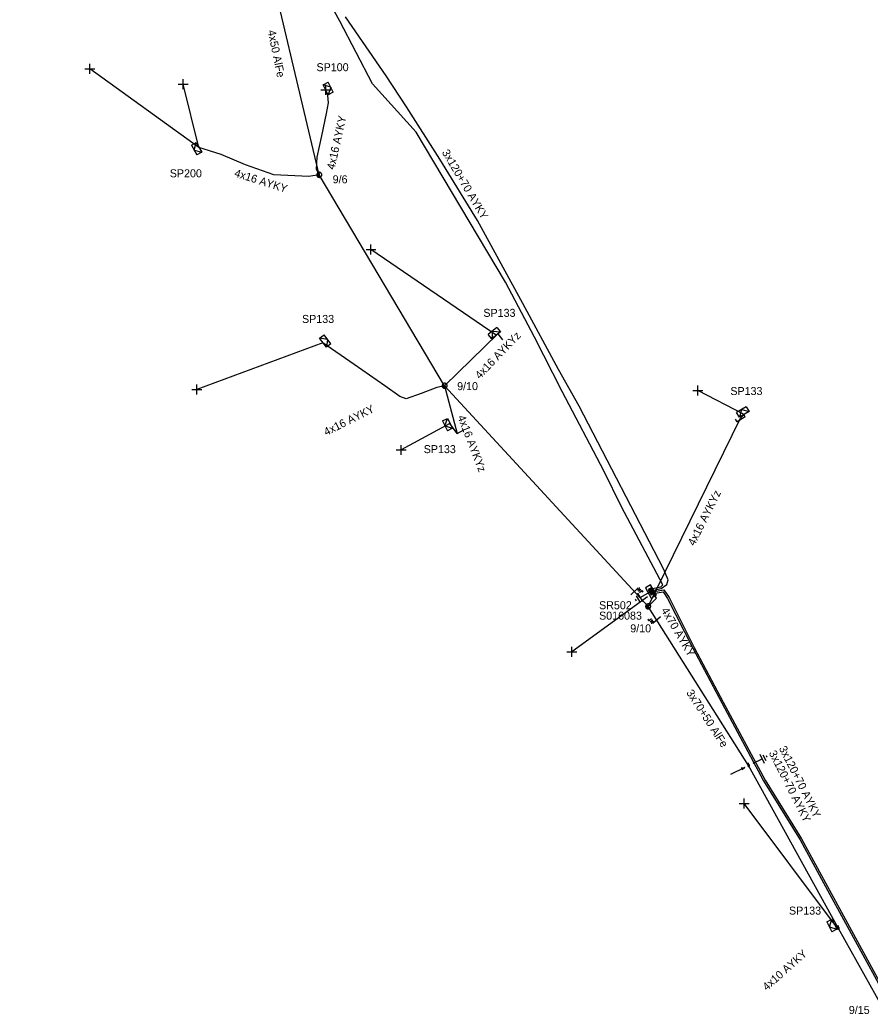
# Model space of a CAD drawing. Extents: x -717562 to -713845, y -1151196 to -1143903.
# Drawn here: x -717142.1 to -717035.8, y -1144570.4 to -1144446.2 of the extents above; entities that cross this region are included whole.
import ezdxf

# ---------------------------------------------------------------- set-up
doc = ezdxf.new("R2010")
doc.units = 0
for name, color, linetype in [('Vrstva 1', 7, 'Continuous'), ('Vrstva 12', 7, 'Continuous'), ('Vrstva 13', 7, 'Continuous'), ('Vrstva 14', 7, 'Continuous'), ('Vrstva 15', 7, 'Continuous'), ('Vrstva 18', 7, 'Continuous'), ('Vrstva 2', 7, 'Continuous'), ('Vrstva 28', 7, 'Continuous'), ('Vrstva 29', 7, 'Continuous'), ('Vrstva 30', 7, 'Continuous'), ('Vrstva 31', 7, 'Continuous'), ('Vrstva 33', 7, 'Continuous'), ('Vrstva 34', 7, 'Continuous'), ('Vrstva 5', 7, 'Continuous'), ('Vrstva 52', 7, 'Continuous'), ('Vrstva 54', 7, 'Continuous'), ('Vrstva 55', 7, 'Continuous'), ('Vrstva 59', 7, 'Continuous'), ('Vrstva 6', 7, 'Continuous'), ('Vrstva 8', 7, 'Continuous'), ('Vrstva 9', 7, 'Continuous')]:
    doc.layers.add(name, color=color, linetype=linetype)

# ---------------------------------------------------------------- blocks, each defined once
blk = doc.blocks.new('NN440')
at = {"layer": 'Vrstva 2'}
for points in [[(0.63, 0), (0.63, 0.06), (0.62, 0.13), (0.6, 0.19), (0.58, 0.25), (0.55, 0.31), (0.51, 0.37), (0.47, 0.42), (0.42, 0.46), (0.37, 0.51), (0.32, 0.54), (0.26, 0.57), (0.2, 0.59), (0.13, 0.61), (0.07, 0.62), (0, 0.63), (-0.06, 0.62), (-0.13, 0.61), (-0.19, 0.59), (-0.26, 0.57), (-0.31, 0.54), (-0.37, 0.51), (-0.42, 0.46), (-0.47, 0.42), (-0.51, 0.37), (-0.54, 0.31), (-0.57, 0.25), (-0.6, 0.19), (-0.62, 0.13), (-0.63, 0.06), (-0.63, 0), (-0.63, -0.07), (-0.62, -0.14), (-0.6, -0.2), (-0.57, -0.26), (-0.54, -0.32), (-0.51, -0.37), (-0.47, -0.43), (-0.42, -0.47), (-0.37, -0.51), (-0.31, -0.55), (-0.26, -0.58), (-0.19, -0.6), (-0.13, -0.62), (-0.06, -0.63), (0, -0.63), (0.07, -0.63), (0.13, -0.62), (0.2, -0.6), (0.26, -0.58), (0.32, -0.55), (0.37, -0.51), (0.42, -0.47), (0.47, -0.43), (0.51, -0.37), (0.55, -0.32), (0.58, -0.26), (0.6, -0.2), (0.62, -0.14), (0.63, -0.07), (0.63, 0)], [(-0.63, 0), (0.63, 0)], [(-0.6, -0.18), (0.57, -0.18)], [(-0.51, -0.32), (0.5, -0.32)], [(-0.37, -0.47), (0.35, -0.47)]]:
    blk.add_lwpolyline(points, dxfattribs=at)
blk = doc.blocks.new('NN840')
at = {"layer": 'Vrstva 15'}
for points in [[(0, 0.62), (0, -0.63)], [(-0.75, -0.71), (-0.75, -0.66)], [(-0.73, -0.76), (-0.75, -0.71)], [(-0.66, -0.8), (-0.73, -0.76)], [(-0.63, -0.8), (-0.66, -0.8)], [(-0.56, -0.76), (-0.63, -0.8)], [(-0.54, -0.71), (-0.56, -0.76)], [(-0.54, -0.38), (-0.54, -0.71)], [(-0.33, -0.38), (-0.33, -0.8)], [(-0.33, -0.64), (-0.13, -0.38)], [(-0.26, -0.56), (-0.09, -0.8)]]:
    blk.add_lwpolyline(points, dxfattribs=at)
blk = doc.blocks.new('NN565')
at = {"layer": 'Vrstva 2'}
for points in [[(0.01, 0.53), (0.01, 2.53)], [(0.16, 0.94), (0.01, 0.53), (-0.12, 0.94)]]:
    blk.add_lwpolyline(points, dxfattribs=at)
blk = doc.blocks.new('NN800')
at = {"layer": 'Vrstva 1'}
for points in [[(-0.44, 0.44), (0.44, -0.44)], [(-0.44, -0.44), (0.44, 0.44)]]:
    blk.add_lwpolyline(points, dxfattribs=at)
blk = doc.blocks.new('NN620')
at = {"layer": 'Vrstva 8'}
for points in [[(0.75, 0), (-0.75, 0)], [(-0.75, 0), (-0.75, -0.75)], [(0.75, -0.75), (0.75, 0)], [(-0.75, -0.75), (0.75, -0.75)], [(0.37, -0.18), (-0.38, -0.18)], [(-0.38, -0.18), (-0.38, -0.56)], [(-0.38, -0.56), (0.37, -0.56)], [(0.32, -0.23), (-0.33, -0.23)], [(-0.33, -0.23), (-0.33, -0.51)], [(-0.33, -0.51), (0.32, -0.51)], [(0.27, -0.27), (-0.28, -0.27)], [(-0.28, -0.27), (-0.28, -0.46)], [(-0.28, -0.46), (0.27, -0.46)], [(0.23, -0.32), (-0.23, -0.32)], [(-0.23, -0.32), (-0.23, -0.42)], [(-0.23, -0.42), (0.23, -0.42)], [(-0.19, -0.37), (0.19, -0.37)], [(0.23, -0.42), (0.23, -0.32)], [(0.27, -0.46), (0.27, -0.27)], [(0.32, -0.51), (0.32, -0.23)], [(0.37, -0.56), (0.37, -0.18)]]:
    blk.add_lwpolyline(points, dxfattribs=at)
blk = doc.blocks.new('NN630')
at = {"layer": 'Vrstva 9'}
for points in [[(0, -0.7), (-0.7, 0)], [(-0.7, -0.7), (-0.7, 0), (0.7, 0), (0.7, -0.7)], [(-0.7, -0.7), (0.7, -0.7)], [(0, -0.7), (0.7, 0)]]:
    blk.add_lwpolyline(points, dxfattribs=at)
blk = doc.blocks.new('NN810')
at = {"layer": 'Vrstva 14'}
for points in [[(0, -0.64), (0, -1.89)], [(0.63, -1.89), (-0.62, -1.89)], [(0.39, -2.2), (-0.4, -2.2)], [(0, -2.52), (-0.12, -2.52)], [(0.14, -2.52), (0, -2.52)]]:
    blk.add_lwpolyline(points, dxfattribs=at)
blk = doc.blocks.new('NN500')
at = {"layer": 'Vrstva 2'}
for points in [[(0, -0.24), (0.02, -0.23), (0.05, -0.23), (0.07, -0.22), (0.09, -0.22), (0.12, -0.2), (0.14, -0.19), (0.16, -0.18), (0.17, -0.16), (0.19, -0.14), (0.2, -0.12), (0.21, -0.1), (0.22, -0.07), (0.23, -0.05), (0.23, -0.02), (0.23, 0), (0.23, 0.02), (0.23, 0.05), (0.22, 0.07), (0.21, 0.1), (0.2, 0.12), (0.19, 0.14), (0.17, 0.16), (0.16, 0.17), (0.14, 0.19), (0.12, 0.2), (0.09, 0.21), (0.07, 0.22), (0.05, 0.23), (0.02, 0.23), (0, 0.23), (-0.03, 0.23), (-0.05, 0.23), (-0.07, 0.22), (-0.1, 0.21), (-0.12, 0.2), (-0.14, 0.19), (-0.16, 0.17), (-0.18, 0.16), (-0.19, 0.14), (-0.2, 0.12), (-0.22, 0.1), (-0.22, 0.07), (-0.23, 0.05), (-0.23, 0.02), (-0.24, 0), (-0.23, -0.02), (-0.23, -0.05), (-0.22, -0.07), (-0.22, -0.1), (-0.2, -0.12), (-0.19, -0.14), (-0.18, -0.16), (-0.16, -0.18), (-0.14, -0.19), (-0.12, -0.2), (-0.1, -0.22), (-0.07, -0.22), (-0.05, -0.23), (-0.03, -0.23), (0, -0.24)], [(0, -0.24), (0.02, -0.23), (0.05, -0.23), (0.07, -0.22), (0.09, -0.22), (0.12, -0.2), (0.14, -0.19), (0.16, -0.18), (0.17, -0.16), (0.19, -0.14), (0.2, -0.12), (0.21, -0.1), (0.22, -0.07), (0.23, -0.05), (0.23, -0.02), (0.23, 0), (0.23, 0.02), (0.23, 0.05), (0.22, 0.07), (0.21, 0.1), (0.2, 0.12), (0.19, 0.14), (0.17, 0.16), (0.16, 0.17), (0.14, 0.19), (0.12, 0.2), (0.09, 0.21), (0.07, 0.22), (0.05, 0.23), (0.02, 0.23), (0, 0.23), (-0.03, 0.23), (-0.05, 0.23), (-0.07, 0.22), (-0.1, 0.21), (-0.12, 0.2), (-0.14, 0.19), (-0.16, 0.17), (-0.18, 0.16), (-0.19, 0.14), (-0.2, 0.12), (-0.22, 0.1), (-0.22, 0.07), (-0.23, 0.05), (-0.23, 0.02), (-0.24, 0), (-0.23, -0.02), (-0.23, -0.05), (-0.22, -0.07), (-0.22, -0.1), (-0.2, -0.12), (-0.19, -0.14), (-0.18, -0.16), (-0.16, -0.18), (-0.14, -0.19), (-0.12, -0.2), (-0.1, -0.22), (-0.07, -0.22), (-0.05, -0.23), (-0.03, -0.23), (0, -0.24)], [(0, -0.21), (0.02, -0.2), (0.04, -0.2), (0.06, -0.2), (0.08, -0.19), (0.1, -0.18), (0.12, -0.17), (0.14, -0.15), (0.15, -0.14), (0.16, -0.12), (0.18, -0.1), (0.19, -0.08), (0.19, -0.06), (0.2, -0.04), (0.2, -0.02), (0.2, 0), (0.2, 0.02), (0.2, 0.04), (0.19, 0.06), (0.19, 0.08), (0.18, 0.1), (0.16, 0.12), (0.15, 0.14), (0.14, 0.15), (0.12, 0.17), (0.1, 0.18), (0.08, 0.19), (0.06, 0.19), (0.04, 0.2), (0.02, 0.2), (0, 0.2), (-0.02, 0.2), (-0.04, 0.2), (-0.06, 0.19), (-0.08, 0.19), (-0.1, 0.18), (-0.12, 0.17), (-0.14, 0.15), (-0.15, 0.14), (-0.17, 0.12), (-0.18, 0.1), (-0.19, 0.08), (-0.2, 0.06), (-0.2, 0.04), (-0.21, 0.02), (-0.21, 0), (-0.21, -0.02), (-0.2, -0.04), (-0.2, -0.06), (-0.19, -0.08), (-0.18, -0.1), (-0.17, -0.12), (-0.15, -0.14), (-0.14, -0.15), (-0.12, -0.17), (-0.1, -0.18), (-0.08, -0.19), (-0.06, -0.2), (-0.04, -0.2), (-0.02, -0.2), (0, -0.21)], [(0, -0.18), (0.02, -0.18), (0.04, -0.17), (0.05, -0.17), (0.07, -0.16), (0.09, -0.15), (0.1, -0.14), (0.12, -0.13), (0.13, -0.12), (0.14, -0.1), (0.15, -0.09), (0.16, -0.07), (0.17, -0.05), (0.17, -0.04), (0.17, -0.02), (0.17, 0), (0.17, 0.02), (0.17, 0.04), (0.17, 0.05), (0.16, 0.07), (0.15, 0.09), (0.14, 0.1), (0.13, 0.12), (0.12, 0.13), (0.1, 0.14), (0.09, 0.15), (0.07, 0.16), (0.05, 0.17), (0.04, 0.17), (0.02, 0.17), (0, 0.18), (-0.02, 0.17), (-0.04, 0.17), (-0.06, 0.17), (-0.07, 0.16), (-0.09, 0.15), (-0.1, 0.14), (-0.12, 0.13), (-0.13, 0.12), (-0.14, 0.1), (-0.15, 0.09), (-0.16, 0.07), (-0.17, 0.05), (-0.17, 0.04), (-0.18, 0.02), (-0.18, 0), (-0.18, -0.02), (-0.17, -0.04), (-0.17, -0.05), (-0.16, -0.07), (-0.15, -0.09), (-0.14, -0.1), (-0.13, -0.12), (-0.12, -0.13), (-0.1, -0.14), (-0.09, -0.15), (-0.07, -0.16), (-0.06, -0.17), (-0.04, -0.17), (-0.02, -0.18), (0, -0.18)], [(0, -0.15), (0.01, -0.15), (0.03, -0.14), (0.04, -0.14), (0.06, -0.13), (0.07, -0.13), (0.08, -0.12), (0.1, -0.11), (0.11, -0.1), (0.12, -0.09), (0.13, -0.07), (0.13, -0.06), (0.14, -0.05), (0.14, -0.03), (0.14, -0.02), (0.14, 0), (0.14, 0.01), (0.14, 0.03), (0.14, 0.04), (0.13, 0.06), (0.13, 0.07), (0.12, 0.09), (0.11, 0.1), (0.1, 0.11), (0.08, 0.12), (0.07, 0.13), (0.06, 0.13), (0.04, 0.14), (0.03, 0.14), (0.01, 0.14), (0, 0.15), (-0.02, 0.14), (-0.03, 0.14), (-0.05, 0.14), (-0.06, 0.13), (-0.07, 0.13), (-0.09, 0.12), (-0.1, 0.11), (-0.11, 0.1), (-0.12, 0.09), (-0.13, 0.07), (-0.13, 0.06), (-0.14, 0.04), (-0.14, 0.03), (-0.15, 0.01), (-0.15, 0), (-0.15, -0.02), (-0.14, -0.03), (-0.14, -0.05), (-0.13, -0.06), (-0.13, -0.07), (-0.12, -0.09), (-0.11, -0.1), (-0.1, -0.11), (-0.09, -0.12), (-0.07, -0.13), (-0.06, -0.13), (-0.05, -0.14), (-0.03, -0.14), (-0.02, -0.15), (0, -0.15)], [(0, -0.12), (0.01, -0.12), (0.02, -0.11), (0.03, -0.11), (0.05, -0.11), (0.06, -0.1), (0.07, -0.09), (0.08, -0.09), (0.09, -0.08), (0.09, -0.07), (0.1, -0.06), (0.11, -0.05), (0.11, -0.04), (0.11, -0.02), (0.11, -0.01), (0.12, 0), (0.11, 0.01), (0.11, 0.02), (0.11, 0.04), (0.11, 0.05), (0.1, 0.06), (0.09, 0.07), (0.09, 0.08), (0.08, 0.09), (0.07, 0.09), (0.06, 0.1), (0.05, 0.11), (0.03, 0.11), (0.02, 0.11), (0.01, 0.12), (0, 0.12), (-0.01, 0.12), (-0.03, 0.11), (-0.04, 0.11), (-0.05, 0.11), (-0.06, 0.1), (-0.07, 0.09), (-0.08, 0.09), (-0.09, 0.08), (-0.1, 0.07), (-0.1, 0.06), (-0.11, 0.05), (-0.11, 0.04), (-0.12, 0.02), (-0.12, 0.01), (-0.12, 0), (-0.12, -0.01), (-0.12, -0.02), (-0.11, -0.04), (-0.11, -0.05), (-0.1, -0.06), (-0.1, -0.07), (-0.09, -0.08), (-0.08, -0.09), (-0.07, -0.09), (-0.06, -0.1), (-0.05, -0.11), (-0.04, -0.11), (-0.03, -0.11), (-0.01, -0.12), (0, -0.12)], [(0, -0.09), (0.01, -0.09), (0.02, -0.09), (0.03, -0.08), (0.03, -0.08), (0.04, -0.08), (0.05, -0.07), (0.06, -0.07), (0.06, -0.06), (0.07, -0.05), (0.07, -0.04), (0.08, -0.04), (0.08, -0.03), (0.08, -0.02), (0.09, -0.01), (0.09, 0), (0.09, 0.01), (0.08, 0.02), (0.08, 0.03), (0.08, 0.03), (0.07, 0.04), (0.07, 0.05), (0.06, 0.06), (0.06, 0.06), (0.05, 0.07), (0.04, 0.07), (0.03, 0.08), (0.03, 0.08), (0.02, 0.08), (0.01, 0.09), (0, 0.09), (-0.01, 0.09), (-0.02, 0.08), (-0.03, 0.08), (-0.04, 0.08), (-0.04, 0.07), (-0.05, 0.07), (-0.06, 0.06), (-0.07, 0.06), (-0.07, 0.05), (-0.08, 0.04), (-0.08, 0.03), (-0.08, 0.03), (-0.09, 0.02), (-0.09, 0.01), (-0.09, 0), (-0.09, -0.01), (-0.09, -0.02), (-0.08, -0.03), (-0.08, -0.04), (-0.08, -0.04), (-0.07, -0.05), (-0.07, -0.06), (-0.06, -0.07), (-0.05, -0.07), (-0.04, -0.08), (-0.04, -0.08), (-0.03, -0.08), (-0.02, -0.09), (-0.01, -0.09), (0, -0.09)], [(0, -0.06), (0, -0.06), (0.01, -0.06), (0.02, -0.05), (0.02, -0.05), (0.03, -0.05), (0.03, -0.05), (0.04, -0.04), (0.04, -0.04), (0.05, -0.03), (0.05, -0.03), (0.05, -0.02), (0.05, -0.02), (0.05, -0.01), (0.06, -0.01), (0.06, 0), (0.06, 0.01), (0.05, 0.01), (0.05, 0.02), (0.05, 0.02), (0.05, 0.03), (0.05, 0.03), (0.04, 0.04), (0.04, 0.04), (0.03, 0.05), (0.03, 0.05), (0.02, 0.05), (0.02, 0.05), (0.01, 0.06), (0, 0.06), (0, 0.06), (-0.01, 0.06), (-0.01, 0.06), (-0.02, 0.05), (-0.02, 0.05), (-0.03, 0.05), (-0.03, 0.05), (-0.04, 0.04), (-0.04, 0.04), (-0.05, 0.03), (-0.05, 0.03), (-0.05, 0.02), (-0.06, 0.02), (-0.06, 0.01), (-0.06, 0.01), (-0.06, 0), (-0.06, -0.01), (-0.06, -0.01), (-0.06, -0.02), (-0.05, -0.02), (-0.05, -0.03), (-0.05, -0.03), (-0.04, -0.04), (-0.04, -0.04), (-0.03, -0.05), (-0.03, -0.05), (-0.02, -0.05), (-0.02, -0.05), (-0.01, -0.06), (-0.01, -0.06), (0, -0.06)], [(0, -0.03), (0, -0.03), (0, -0.03), (0.01, -0.03), (0.01, -0.03), (0.01, -0.02), (0.02, -0.02), (0.02, -0.02), (0.02, -0.02), (0.02, -0.02), (0.02, -0.01), (0.02, -0.01), (0.03, -0.01), (0.03, -0.01), (0.03, 0), (0.03, 0), (0.03, 0), (0.03, 0.01), (0.03, 0.01), (0.02, 0.01), (0.02, 0.01), (0.02, 0.02), (0.02, 0.02), (0.02, 0.02), (0.02, 0.02), (0.01, 0.02), (0.01, 0.02), (0.01, 0.03), (0, 0.03), (0, 0.03), (0, 0.03), (0, 0.03), (-0.01, 0.03), (-0.01, 0.03), (-0.01, 0.02), (-0.02, 0.02), (-0.02, 0.02), (-0.02, 0.02), (-0.02, 0.02), (-0.02, 0.02), (-0.03, 0.01), (-0.03, 0.01), (-0.03, 0.01), (-0.03, 0.01), (-0.03, 0), (-0.03, 0), (-0.03, 0), (-0.03, -0.01), (-0.03, -0.01), (-0.03, -0.01), (-0.03, -0.01), (-0.02, -0.02), (-0.02, -0.02), (-0.02, -0.02), (-0.02, -0.02), (-0.02, -0.02), (-0.01, -0.03), (-0.01, -0.03), (-0.01, -0.03), (0, -0.03), (0, -0.03)], [(0.23, 0), (0.7, 0)]]:
    blk.add_lwpolyline(points, dxfattribs=at)
blk = doc.blocks.new('NN510')
at = {"layer": 'Vrstva 2'}
blk.add_lwpolyline([(0, 0), (0, 0.94)], dxfattribs=at)
blk = doc.blocks.new('NN515')
at = {"layer": 'Vrstva 2'}
for points in [[(-0.59, 0.18), (0.59, 0.18)], [(-0.59, 0.18), (-0.59, -0.18)], [(0.59, 0.18), (0.59, -0.18)]]:
    blk.add_lwpolyline(points, dxfattribs=at)

msp = doc.modelspace()

# ---------------------------------------------------------------- linework, layer by layer
at = {"layer": 'Vrstva 1'}
for points in [[(-717063.54, -1144519.5), (-717088.98, -1144491.92), (-717104.65, -1144465.56), (-717112.11, -1144434.03), (-717129.32, -1144395.14), (-717142.08, -1144353.91)], [(-717034.22, -1144569.65), (-717039.77, -1144559.73), (-717050.99, -1144539.38), (-717063.54, -1144519.5)]]:
    msp.add_lwpolyline(points, dxfattribs=at)
at = {"layer": 'Vrstva 5'}
for points in [[(-717063.54, -1144519.5), (-717062.48, -1144518.46), (-717062.73, -1144518.05)], [(-717062.79, -1144517.65), (-717061.58, -1144517.41), (-717060.93, -1144518.39), (-717057.78, -1144524.64), (-717054.16, -1144531.46), (-717048.93, -1144541.21), (-717044.37, -1144548.56), (-717040.64, -1144555.42), (-717033.37, -1144568.72)], [(-717062.67, -1144517.85), (-717061.66, -1144517.66), (-717061.11, -1144518.49), (-717057.96, -1144524.73), (-717054.34, -1144531.56), (-717049.11, -1144541.31), (-717044.55, -1144548.66), (-717040.82, -1144555.52), (-717033.55, -1144568.82)]]:
    msp.add_lwpolyline(points, dxfattribs=at)
at = {"layer": 'Vrstva 52'}
for points in [[(-717063.01, -1144517.27), (-717061.95, -1144517.07), (-717061.69, -1144516.79), (-717066.89, -1144507.06), (-717069.09, -1144502.54), (-717074.3, -1144492.66), (-717077.75, -1144485.87), (-717081.38, -1144478.98), (-717092.54, -1144460.21), (-717097.98, -1144454.18), (-717102.09, -1144446.37), (-717104.09, -1144442.69)], [(-717062.87, -1144517.45), (-717061.93, -1144517.27), (-717061.22, -1144516.76), (-717061.05, -1144516.17), (-717061.63, -1144514.81), (-717072.15, -1144494.49), (-717074.74, -1144489.87), (-717079.22, -1144481.64), (-717084.86, -1144471.25), (-717089.59, -1144463.62), (-717093.74, -1144457.05), (-717096.28, -1144453.2), (-717101.37, -1144445.81)], [(-717104.65, -1144465.56), (-717105.02, -1144464.85), (-717104.93, -1144463.35), (-717104.34, -1144460.69), (-717103.73, -1144457.91), (-717103.51, -1144456.55), (-717103.57, -1144455.63), (-717103.84, -1144454.93)], [(-717104.65, -1144465.56), (-717105.94, -1144465.77), (-717110.34, -1144465.58), (-717113.87, -1144464.32), (-717116.92, -1144463.03), (-717119.69, -1144462.13)], [(-717088.98, -1144491.92), (-717089.97, -1144492.15), (-717091.9, -1144492.9), (-717093.8, -1144493.57), (-717094.58, -1144493.27), (-717096.47, -1144491.95), (-717100.28, -1144489.27), (-717104.19, -1144486.55)], [(-717039.77, -1144559.73), (-717040.26, -1144559.22)]]:
    msp.add_lwpolyline(points, dxfattribs=at)
at = {"layer": 'Vrstva 54'}
for points in [[(-717088.98, -1144491.92), (-717082.35, -1144485.44), (-717082.56, -1144485.62)], [(-717088.98, -1144491.92), (-717087.42, -1144497.88), (-717088.32, -1144496.62)], [(-717063.54, -1144519.5), (-717052.01, -1144495.96), (-717051.54, -1144495.51)]]:
    msp.add_lwpolyline(points, dxfattribs=at)
at = {"layer": 'Vrstva 59'}
for points in [[(-717119.69, -1144462.13), (-717133.32, -1144452.32)], [(-717119.69, -1144462.13), (-717121.68, -1144454.22)], [(-717082.56, -1144485.62), (-717098.19, -1144474.88)], [(-717104.19, -1144486.55), (-717119.94, -1144492.38)], [(-717051.54, -1144495.51), (-717057.32, -1144492.52)], [(-717088.32, -1144496.62), (-717094.4, -1144499.95)], [(-717063.61, -1144518.31), (-717073.09, -1144525.17)], [(-717040.26, -1144559.22), (-717051.56, -1144544.13)]]:
    msp.add_lwpolyline(points, dxfattribs=at)

# ---------------------------------------------------------------- block references
at = {"layer": 'Vrstva 13', "yscale": 0.5}
for name, p, xscale, rotation in [('NN440', (-717104.65, -1144465.56), 0.5000000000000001, -78.3947500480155), ('NN440', (-717088.98, -1144491.92), 0.5, -47.582841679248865), ('NN440', (-717063.54, -1144519.5), 0.5, -47.582841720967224), ('NN500', (-717050.99, -1144539.38), 0.5, 90), ('NN500', (-717039.77, -1144559.73), 0.5, 90)]:
    msp.add_blockref(name, p, dxfattribs=dict(at, xscale=xscale, rotation=rotation))
at = {"layer": 'Vrstva 13'}
for name, p, rotation in [('NN510', (-717082.35, -1144485.44), -140.47282500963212), ('NN515', (-717052.01, -1144495.96), -149.70596114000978), ('NN510', (-717087.42, -1144497.88), -62.28666109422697), ('NN565', (-717050.99, -1144539.38), 116.79325832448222)]:
    msp.add_blockref(name, p, dxfattribs=dict(at, rotation=rotation))
at = {"layer": 'Vrstva 15'}
for p, rotation in [((-717062.87, -1144517.45), -60.67915007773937), ((-717050.99, -1144539.38), 116.79325826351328)]:
    msp.add_blockref('NN810', p, dxfattribs=dict(at, rotation=rotation))
at = {"layer": 'Vrstva 18'}
for p, rotation in [((-717065.27, -1144517.62), 132.41773054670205), ((-717062.47, -1144521.22), -49.70289987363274)]:
    msp.add_blockref('NN840', p, dxfattribs=dict(at, rotation=rotation))
at = {"layer": 'Vrstva 28', "rotation": -60.67915007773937}
msp.add_blockref('NN620', (-717062.87, -1144517.45), dxfattribs=at)
at = {"layer": 'Vrstva 31'}
for p, rotation in [((-717103.84, -1144454.93), 116.87227798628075), ((-717119.69, -1144462.13), -60.70194161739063), ((-717082.56, -1144485.62), -140.47282500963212), ((-717104.19, -1144486.55), 126.93596312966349), ((-717051.54, -1144495.51), -149.70596114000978), ((-717088.32, -1144496.62), -62.37043489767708), ((-717040.26, -1144559.22), -63.20674167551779)]:
    msp.add_blockref('NN630', p, dxfattribs=dict(at, rotation=rotation))
at = {"layer": 'Vrstva 34'}
for p, rotation in [((-717133.32, -1144452.32), 45), ((-717121.68, -1144454.22), 45), ((-717103.84, -1144454.93), 45.00000009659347), ((-717098.19, -1144474.88), 44.99999995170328), ((-717119.94, -1144492.38), 44.99999995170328), ((-717057.32, -1144492.52), 44.99999995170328), ((-717094.4, -1144499.95), 44.99999995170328), ((-717073.09, -1144525.17), 45), ((-717051.56, -1144544.13), 45)]:
    msp.add_blockref('NN800', p, dxfattribs=dict(at, rotation=rotation))

# ---------------------------------------------------------------- texts
at = {"layer": 'Vrstva 12'}
for s, p in [('9/6', (-717102.98, -1144466.62)), ('9/10', (-717087.42, -1144492.47)), ('9/10', (-717065.78, -1144522.74)), ('9/15', (-717038.46, -1144570.43))]:
    msp.add_text(s, height=1, dxfattribs=at).set_placement(p)
at = {"layer": 'Vrstva 2'}
for s, rotation, p in [('4x50 AlFe', 281.605, (-717111.11, -1144447.57)), ('3x70+50 AlFe', 302.897, (-717058.82, -1144530.28))]:
    msp.add_text(s, height=1, rotation=rotation, dxfattribs=at).set_placement(p)
at = {"layer": 'Vrstva 29'}
msp.add_text('S016083', height=1, dxfattribs=at).set_placement((-717069.68, -1144521.15))
at = {"layer": 'Vrstva 30'}
msp.add_text('SR502', height=1, dxfattribs=at).set_placement((-717069.68, -1144519.85))
at = {"layer": 'Vrstva 33'}
for s, p in [('SP100', (-717105, -1144452.61)), ('SP200', (-717123.34, -1144465.87)), ('SP133', (-717084.14, -1144483.31)), ('SP133', (-717106.81, -1144484.07)), ('SP133', (-717053.27, -1144493.08)), ('SP133', (-717091.6, -1144500.34)), ('SP133', (-717045.94, -1144558.01))]:
    msp.add_text(s, height=1, dxfattribs=at).set_placement(p)
at = {"layer": 'Vrstva 54'}
for s, rotation, p in [('4x16 AYKY', 77.437, (-717102.75, -1144464.98)), ('3x120+70 AYKY', 300.735, (-717089.37, -1144462.75)), ('4x16 AYKY', 342.392, (-717115.35, -1144465.75)), ('4x16 AYKY', 26.572, (-717103.78, -1144498.2)), ('4x10 AYKY', 41.504, (-717048.71, -1144567.58))]:
    msp.add_text(s, height=1, rotation=rotation, dxfattribs=at).set_placement(p)
at = {"layer": 'Vrstva 55'}
for rotation, p in [(46.141, (-717084.58, -1144491.15)), (291.127, (-717087.39, -1144495.81)), (63.435, (-717057.76, -1144512))]:
    msp.add_text('4x16 AYKYz', height=1, rotation=rotation, dxfattribs=at).set_placement(p)
at = {"layer": 'Vrstva 6'}
for s, rotation, p in [('4x70 AYKY', 300.343, (-717061.96, -1144519.98)), ('3x120+70 AYKY', 296.822, (-717047.23, -1144537.23)), ('3x120+70 AYKY', 296.822, (-717048.49, -1144537.8))]:
    msp.add_text(s, height=1, rotation=rotation, dxfattribs=at).set_placement(p)

doc.saveas('drawing.dxf')
